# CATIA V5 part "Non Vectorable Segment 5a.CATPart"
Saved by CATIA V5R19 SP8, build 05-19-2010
Part number: Non Vectorable Segment 5a
Bounding box of the stored display mesh (mm): x -20 to 20, y 721 to 832.294, z 387 to 409
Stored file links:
  G:\EU_thinkMotion\CFAO_2010\MMS_groupe3\MMS_groupe3\A reprendre\fovide\fovide\Non Vectorable Segment 5a.CATPart
  G:\EU_thinkMotion\CFAO_2010\MMS_groupe3\MMS_groupe3\A reprendre\fovide\fovide\fovide.CATProduct
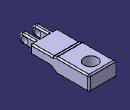
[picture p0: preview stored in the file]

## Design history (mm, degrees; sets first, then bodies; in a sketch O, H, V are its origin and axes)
Set1
  Plane1: linked copy from another document
  Point1 "Point.G": linked copy from another document
  Line1: linked copy from another document
  Plane2: linked copy from another document
  Point2 "Point.H": linked copy from another document
  Line2: linked copy from another document
  Line3: linked copy from another document
Body1 (main body)
  Sketch1 on Plane1, origin (0, 0, 0), H (0, 1, 0), V (0, 0, 1)
    line L1 (784.2945, 409) -> (832.2945, 409)
    line L2 (832.2945, 409) -> (832.2945, 387)
    line L3 (832.2945, 387) -> (784.7408, 387)
    line L4 (784.2945, 409) -> (779, 407)
    line L5 (779, 407) -> (745, 407)
    reference projected point E1 (815, 400) from Point1
    line L6 (784.7408, 387) -> (775, 393)
    line L7 (775, 393) -> (745, 393)
    line L8 (745, 407) -> (745, 393)
    reference projected line E2 (815, 400) -> (730, 400) from Line1
    reference projected point E3 (730, 400) from Point2
    length L1 = 48
    length L2 = 22
    distance L1 E1 = 9
    length L5 = 34
    length L7 = 30
    distance E2 L5 = 7
    distance L8 E3 = 15
    length L8 = 14
    horizontal: L1 H, L3 H, L5 H, L7 H
    vertical: L2 V, L8 V
  Pad1: profile Sketch1, direction (1, 0, 0), length 20, mirrored extent
  Sketch2 on Plane2, origin (0, 0, 400), H (1, 0, 0), V (0, 1, 0)
    line L1 (-13, 745) -> (-6, 745)
    line L2 (-6, 745) -> (-6, 721)
    line L3 (-6, 721) -> (-13, 721)
    line L4 (-13, 721) -> (-13, 745)
    reference projected line E1 (-20, 745) -> (20, 745) from edge [face of Pad1 from Sketch1.L8 | face of Pad1 from Sketch1.L5]
    reference projected line E2 (0, 815) -> (0, 730) from Line1
    line L5 (6, 745) -> (13, 745)
    line L6 (13, 745) -> (13, 721)
    line L7 (13, 721) -> (6, 721)
    line L8 (6, 721) -> (6, 745)
    reference projected line E3 (-20, 745) -> (20, 745) from edge [face of Pad1 from Sketch1.L8 | face of Pad1 from Sketch1.L5]
    reference projected line E4 (0, 815) -> (0, 730) from Line1
    length L4 = 24
    length L3 = 7
    distance L2 E2 = 6
    length L7 = 7
    distance L8 E4 = 6
    horizontal: L1 H, L3 H, L5 H, L7 H
    vertical: L2 V, L4 V, L6 V, L8 V
    coincidence: L1 E1, L5 E3, L7 L3
  Pad2: profile Sketch2, direction (0, 0, 1), length 7, mirrored extent
  Fillet1: radius 5, on edge [face of Pad2 from Sketch2.L7 | face of Pad2]; edge [face of Pad2 | face of Pad2 from Sketch2.L7]; edge [face of Pad2 | face of Pad2 from Sketch2.L3]; edge [face of Pad2 from Sketch2.L3 | face of Pad2]
  Fillet2: radius 2, on face of Pad2 (x2); face of Pad1 from Sketch1.L4; face of Pad1 from Sketch1.L1; end face of Pad1; face of Pad1 from Sketch1.L3; face of Pad1 from Sketch1.L6
  Sketch3 on face of Pad2 from Sketch2.L6, origin (13, 730, 400), H (0, 1, 0), V (0, 0, 1)
    point P1 (0, 0)
    intersected point E1 (0, 0) from Line2
    coincidence: E1 P1
  Hole1: placed by Sketch3, at (13, 730, 400) direction (-1, 0, 0), diameter 10, through (limit type 3)
  Sketch4 on face of Pad1 from Sketch1.L1, origin (0, 815, 409), H (1, 0, 0), V (0, 1, 0)
    point P1 (0, 0)
    intersected point E1 (0, 0) from Line3
    coincidence: E1 P1
  Hole2: placed by Sketch4, at (0, 815, 409) direction (0, 0, -1), diameter 20, through (limit type 3)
